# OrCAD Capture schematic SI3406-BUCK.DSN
size B; title: Si3404-Buck; rev: 2.2; note: SI3406-BUCK
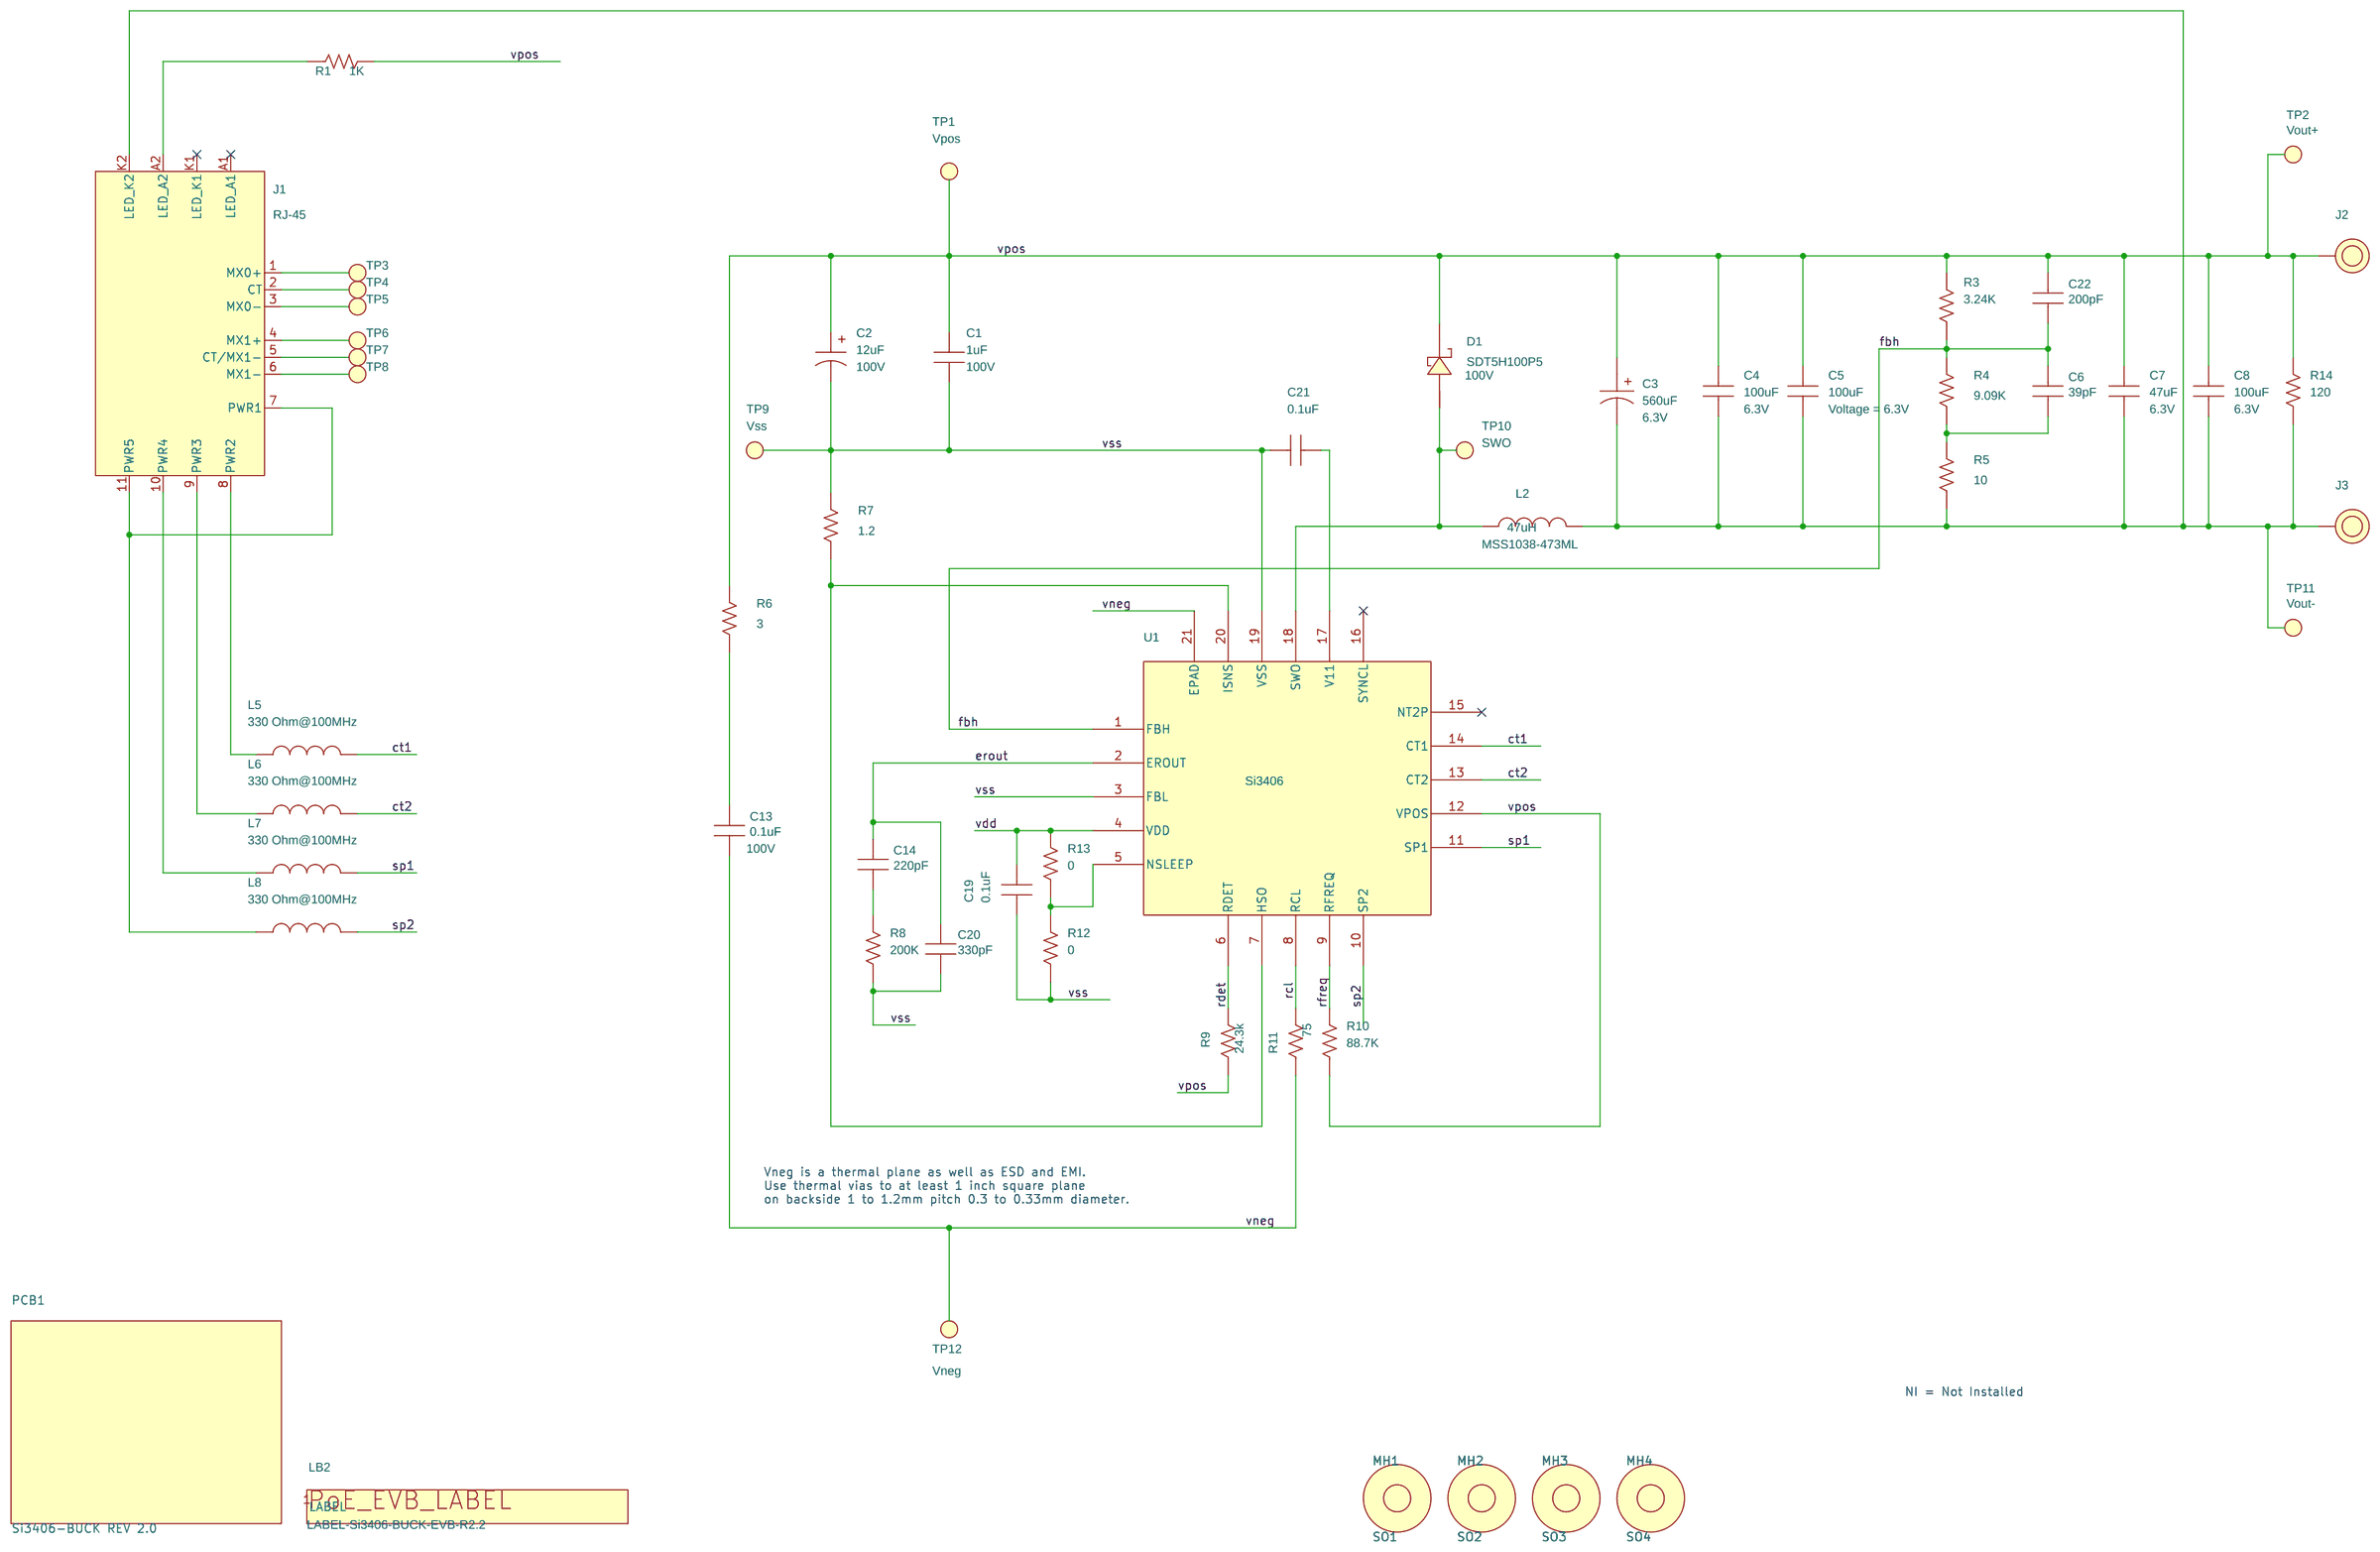
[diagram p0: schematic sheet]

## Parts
C1  1uF  [C1210]
C2  12uF  [C2.5X6.3MM-RAD]
C3  560uF  [C3.5X8MM-RAD]
C4  100uF  [C1210]
C5  100uF  [C1210]
C6  39pF  [C0805]
C7  47uF  [C0805]
C8  100uF  [C1210]
C13  0.1uF  [C0805]
C14  220pF  [C0805]
C19  0.1uF  [C0805]
C20  330pF  [C0805]
C21  0.1uF  [C0805]
C22  200pF  [C0805]
D1  SDT5H100P5  [POWERDI-5]
J1  RJ-45  [RJ45-SI-52004]
J2  BND_POST  [BANANA-JACK]
J3  BND_POST  [BANANA-JACK]
L2  47uH  [IND-MSS1038]
L5  330 Ohm@100MHz  [L0805]
L6  330 Ohm@100MHz  [L0805]
L7  330 Ohm@100MHz  [L0805]
L8  330 Ohm@100MHz  [L0805]
LB2  LABEL-Si3406-BUCK-EVB-R2.2  [PTL-14-717]
MH1  4-40  [MH-125NP]
MH2  4-40  [MH-125NP]
MH3  4-40  [MH-125NP]
MH4  4-40  [MH-125NP]
PCB1  Si3406-BUCK REV 2.0  [N/A]
R1  1K  [R0805]
R3  3.24K  [R0805]
R4  9.09K  [R0805]
R5  10  [R0805]
R6  3  [R0805]
R7  1.2  [R0805]
R8  200K  [R0805]
R9  24.3k  [R0805]
R10  88.7K  [R0805]
R11  75  [R0805]
R12  0  [R0805]
R13  0  [R0805]
R14  120  [R0805]
SO1  STANDOFF
SO2  STANDOFF
SO3  STANDOFF
SO4  STANDOFF
TP1  BLACK  [TESTPOINT]
TP2  BLACK  [TESTPOINT]
TP3  BLACK  [TESTPOINT]
TP4  BLACK  [TESTPOINT]
TP5  BLACK  [TESTPOINT]
TP6  BLACK  [TESTPOINT]
TP7  BLACK  [TESTPOINT]
TP8  BLACK  [TESTPOINT]
TP9  BLACK  [TESTPOINT]
TP10  BLACK  [TESTPOINT]
TP11  BLACK  [TESTPOINT]
TP12  BLACK  [TESTPOINT]
U1  Si3406  [QFN20N5X5P0.8]

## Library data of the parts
C1 = CAP_NP: CAP, 1uF, 100V, ±10%, X7R, 1210; Manufacturer: Venkel; ManufacturerPN: C1210X7R101-105K; SiLabsPN: C1210X7R101-105K; Tolerance: ±10%; Type: X7R; Voltage: 100V; Datasheet: PID_C.pdf
C2 = CAP_POL_ALT: CAP, 12uF, 100V, ±20%, AL, 6.3X11.2MM; Manufacturer: Panasonic; ManufacturerPN: EEUFC2A120; SiLabsPN: EEUFC2A120; Tolerance: ±20%; Type: Alum_Elec; Voltage: 100V; Datasheet: ABA0000CE22.pdf
C3 = CAP_POL: CAP, 560uF, 6.3V, ±20%, AL, 8.0X11.5MM; Manufacturer: Panasonic; ManufacturerPN: EEUFM0J561; Part_Type: CAP/POL; SiLabsPN: EEUFM0J561; Tolerance: ±20%; Type: Alum_Elec; Voltage: 6.3V; Datasheet: ABA0000CE108.pdf
C4 C5 C8 = CAP_NP: CAP, 100uF, 6.3V, ±10%, X5R, 1210; Manufacturer: Venkel; ManufacturerPN: C1210X5R6R3-107K; SiLabsPN: C1210X5R6R3-107K; Tolerance: ±10%; Type: X5R; Voltage: 6.3V; Datasheet: PID_C.pdf
C6 = CAP_NP: CAP, 39pF, 25V, ±1%, C0G, 0805; Manufacturer: Venkel; ManufacturerPN: C0805C0G250-390FNP; SiLabsPN: C0805C0G250-390F; Tolerance: ±1%; Type: C0G; Voltage: 25V; Datasheet: PID_C.pdf
C7 = CAP_NP: CAP, 47uF, 6.3V, ±20%, X5R, 0805; Manufacturer: Venkel; ManufacturerPN: C0805X5R6R3-476M; SiLabsPN: C0805X5R6R3-476M; Tolerance: ±20%; Type: X5R; Voltage: 6.3V; Datasheet: PID_C.pdf
C13 = CAP_NP: CAP, 0.1uF, 100V, ±10%, X7R, 0805; Manufacturer: Venkel; ManufacturerPN: C0805X7R101-104K; SiLabsPN: C0805X7R101-104K; Tolerance: ±10%; Type: X7R; Voltage: 100V; Datasheet: PID_C.pdf
C14 = CAP_NP: CAP, 220pF, 50V, ±1%, C0G, 0805; Manufacturer: Venkel; ManufacturerPN: C0805C0G500-221FNE; SiLabsPN: C0805C0G500-221F; Tolerance: ±1%; Type: C0G; Voltage: 50V; Datasheet: PID_C.pdf
C19 C21 = CAP_NP: CAP, 0.1uF, 16V, ±10%, X7R, 0805; Manufacturer: Venkel; ManufacturerPN: C0805X7R160-104K; SiLabsPN: C0805X7R160-104K; Tolerance: ±10%; Type: X7R; Voltage: 16V; Datasheet: PID_C.pdf
C20 = CAP_NP: CAP, 330pF, 50V, ±1%, C0G, 0805; Manufacturer: Venkel; ManufacturerPN: C0805C0G500-331F; SiLabsPN: C0805C0G500-331F; Tolerance: ±1%; Type: C0G; Voltage: 50V; Datasheet: PID_C.pdf
C22 = CAP_NP: CAP, 200pF, 50V, ±1%, C0G, 0805; Manufacturer: Venkel; ManufacturerPN: C0805C0G500-201FNE; SiLabsPN: C0805C0G500-201F; Tolerance: ±1%; Type: C0G; Voltage: 50V; Datasheet: PID_C.pdf
D1 = DIODE_SCHOTTKY_DUAL_ANODE_3PIN: DIO, SCHOTTKY, 100V, 5A, PowerDI-5; Manufacturer: Diodes Inc.; ManufacturerPN: SDT5H100P5-7; Rating: 5A; SiLabsPN: SDT5H100P5-7; Type: Schottky; Voltage: 100V; Datasheet: SDT5H100P5.pdf
J1 = MAGJACK_3: CONN, RJ-45, MAGJACK, 1 Port PoE; Manufacturer: Bel; ManufacturerPN: SI-52003-F; SiLabsPN: SI-52003-F; Type: Receptacle; Datasheet: SI-52003-F.pdf
J2 J3 = BINDING-POST: CONN, BANANA JACK, Threaded uninsulated; Manufacturer: ABBATRON HH SMITH; ManufacturerPN: 101; Part_Type: CON; Rating: 15A; SiLabsPN: 101; Type: BANANA; Datasheet: SD-101.pdf
L2 = INDUCTOR: INDUCTOR, POWER, Shielded, 47uH, ±20%, 1.6A, SMD; Manufacturer: Coilcraft; ManufacturerPN: MSS1038-473ML; Part_Type: IND/SMT; Rating: 1.6A; SiLabsPN: MSS1038-473ML; Tolerance: ±20%; Type: Shielded; Datasheet: mss1038.pdf
L5-L8 = Ferrite_Bead: FERRITE BEAD, 330 Ohm @100MHZ, 0805; Manufacturer: MuRata; ManufacturerPN: BLM21PG331SN1; Part_Type: IND/FB; Rating: 1500mA; SiLabsPN: BLM21PG331SN1; Type: SMT; Datasheet: Murata BLM Ferrites.pdf
LB2 = PoE_EVB_Label: LABEL, PDB, POLYIMIDE, WHITE, 1.00 in. X 0.187 in., FONT 2; Manufacturer: Skyworks; Type: POLYIMIDE, WHITE; Datasheet: Brady TLS2200 Label PTL-14-717.pdf
MH1-MH4 = SCREW-Small: HDW, SCREW, 4-40 x 1/4 in. Pan Head, Slotted, Nylon; Manufacturer: Richco Plastic Co; ManufacturerPN: NSS-4-4-01; SiLabsPN: NSS-4-4-01; Type: SCREW; Datasheet: RichcoPlasticCo_Screws.pdf
PCB1 = PCB: PCB, BARE BOARD, Si3406-BUCK REV 2.0; Manufacturer: Skyworks; Type: BARE PCB
R1 = RES_V: RES, 1K, 1/10W, ±1%, ThickFilm, 0805; Manufacturer: Venkel; ManufacturerPN: CR0805-10W-1001F; Part_Type: RES/SMT; Rating: 1/10W; SiLabsPN: CR0805-10W-1001F; Tolerance: ±1%; Type: ThickFilm; Datasheet: PID_CR.pdf
R3 = RES_V: RES, 3.24K, 1/8W, ±1%, ThickFilm, 0805; Manufacturer: Vishay; ManufacturerPN: CRCW08053K24FKEA; Part_Type: RES/SMT; Rating: 1/8W; SiLabsPN: CR0805-8W-3241F; Tolerance: ±1%; Type: ThickFilm; Datasheet: dcrcwe3-109170.pdf
R4 = RES: RES, 9.09K, 1/10W, ±25PPM, ±0.5%, ThinFilm, 0805; Manufacturer: Susumu; ManufacturerPN: RR1220P-9091-D-M; Rating: 1/10W; SiLabsPN: TFCR0805-10W-E-9091D; Tolerance: ±0.5%; Type: ±25PPM; Datasheet: n_catalog_partition05_en.pdf
R5 = RES: RES, 10 Ohm, 1/10W, ±1%, ThickFilm, 0805; Manufacturer: Venkel; ManufacturerPN: CR0805-10W-10R0F; Rating: 1/10W; SiLabsPN: CR0805-10W-10R0F; Tolerance: ±1%; Type: ThickFilm; Datasheet: PID_CR.pdf
R6 = RES: RES, 3 Ohm, 1/8W, ±1%, ThickFilm, 0805; Manufacturer: Venkel; ManufacturerPN: CR0805-8W-3R00FT; Rating: 1/8W; SiLabsPN: CR0805-8W-3R00F; Tolerance: ±1%; Type: ThickFilm; Datasheet: PID_CR.pdf
R7 = RES: RES, 1.2 Ohm, 1/10W, ±5%, ThickFilm, 0805; Manufacturer: Venkel; ManufacturerPN: CR0805-10W-1R2J; Rating: 1/10W; SiLabsPN: CR0805-10W-1R2J; Tolerance: ±5%; Type: ThickFilm; Datasheet: PID_CR.pdf
R8 = RES: RES, 200K, 1/10W, ±1%, ThickFilm, 0805; Manufacturer: Venkel; ManufacturerPN: CR0805-10W-2003F; Rating: 1/10W; SiLabsPN: CR0805-10W-2003F; Tolerance: ±1%; Type: ThickFilm; Datasheet: PID_CR.pdf
R9 = RES: RES, 24.3k, 1/8W, ±1%, ThickFilm, 0805; Manufacturer: vishay; ManufacturerPN: CRCW080524K3FKEA; Rating: 1/8W; SiLabsPN: CR0805-8W-2432F; Tolerance: ±1%; Type: ThickFilm; Datasheet: dcrcwe3-109170.pdf
R10 = RES: RES, 88.7K, 1/8W, ±1%, ThickFilm, 0805; Manufacturer: Vishay; ManufacturerPN: CRCW080588K7FKEA; Rating: 1/8W; SiLabsPN: CR0805-8W-8872F; Tolerance: ±1%; Type: ThickFilm; Datasheet: dcrcwe3-109170.pdf
R11 = RES: RES, 75 Ohm, 1/10W, ±1%, ThickFilm, 0805; Manufacturer: Venkel; ManufacturerPN: CR0805-10W-75R0F; Rating: 1/10W; SiLabsPN: CR0805-10W-75R0F; Tolerance: ±1%; Type: ThickFilm; Datasheet: PID_CR.pdf
R12 R13 = RES: RES, 0 Ohm, 2A, ThickFilm, 0805; Manufacturer: Venkel; ManufacturerPN: CR0805-10W-000; Rating: 2A; SiLabsPN: CR0805-10W-000; Type: ThickFilm; Datasheet: PID_CR.pdf
R14 = RES: RES, 120 Ohm, 1/10W, ±1%, ThickFilm, 0805; Manufacturer: Venkel; ManufacturerPN: CR0805-10W-1200F; Rating: 1/10W; SiLabsPN: CR0805-10W-1200F; Tolerance: ±1%; Type: ThickFilm; Datasheet: PID_CR.pdf
SO1-SO4 = STANDOFF: HDW, STANDOFF, 4-40 X 1/2" , Nylon; Manufacturer: SPC Technology; ManufacturerPN: 2397; SiLabsPN: 2397; Datasheet: SPC_Technology_spacers.pdf
TP1 = TEST_POINT: TESTPOINT, BLACK, 0.050" LOOP, PTH; Manufacturer: Keystone; ManufacturerPN: 5001; SiLabsPN: 5001; Silk: Vpos; Type: LOOP; Datasheet: Keystone_thm_datasheet.pdf
TP2 = TEST_POINT: TESTPOINT, BLACK, 0.050" LOOP, PTH; Manufacturer: Keystone; ManufacturerPN: 5001; SiLabsPN: 5001; Silk: Vout+; Type: LOOP; Datasheet: Keystone_thm_datasheet.pdf
TP3-TP8 = TEST_POINT: TESTPOINT, BLACK, 0.050" LOOP, PTH; Manufacturer: Keystone; ManufacturerPN: 5001; SiLabsPN: 5001; Silk: <Silk>; Type: LOOP; Datasheet: Keystone_thm_datasheet.pdf
TP9 = TEST_POINT: TESTPOINT, BLACK, 0.050" LOOP, PTH; Manufacturer: Keystone; ManufacturerPN: 5001; SiLabsPN: 5001; Silk: Vss; Type: LOOP; Datasheet: Keystone_thm_datasheet.pdf
TP10 = TEST_POINT: TESTPOINT, BLACK, 0.050" LOOP, PTH; Manufacturer: Keystone; ManufacturerPN: 5001; SiLabsPN: 5001; Silk: SWO; Type: LOOP; Datasheet: Keystone_thm_datasheet.pdf
TP11 = TEST_POINT: TESTPOINT, BLACK, 0.050" LOOP, PTH; Manufacturer: Keystone; ManufacturerPN: 5001; SiLabsPN: 5001; Silk: Vout-; Type: LOOP; Datasheet: Keystone_thm_datasheet.pdf
TP12 = TEST_POINT: TESTPOINT, BLACK, 0.050" LOOP, PTH; Manufacturer: Keystone; ManufacturerPN: 5001; SiLabsPN: 5001; Silk: Vneg; Type: LOOP; Datasheet: Keystone_thm_datasheet.pdf
U1 = Si3406: IC, FULLY-INTEGRATED 802.3-COMPLIANT PoE PD INTERFACE AND LOW-EMI SWITCHING REGULATOR, QFN20; Manufacturer: Skyworks; ManufacturerPN: Si3406-A-GM; SiLabsPN: Si3406-A-GM; Type: PD; Voltage: 120V; Datasheet: si3406x-datasheet.pdf

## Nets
vdd: C19.1 R13.2 U1.4(VDD)
vss: C1.1 C2.2 C19.2 C20.2 C21.1 R7.2 R8.1 R12.1 TP9.1(Point) U1.3(FBL) U1.19(VSS)
ct1: L5.2 U1.14(CT1)
ct2: L6.2 U1.13(CT2)
erout: C14.1 C20.1 U1.2(EROUT)
fbh: C6.1 C22.2 R3.2 R4.2 U1.1(FBH)
LABEL: LB2.1(LABEL)
rcl: R11.2 U1.8(RCL)
rdet: R9.2 U1.6(RDET)
rfreq: R10.2 U1.9(RFREQ)
sp1: L7.2 U1.11(SP1)
sp2: L8.2 U1.10(SP2)
vneg: C13.2 R11.1 TP12.1(Point) U1.21(EPAD)
vpos: C1.2 C2.1 C3.1 C4.1 C5.1 C7.2 C8.1 C22.1 D1.K(CATHODE) J2.1(BP) R1.1 R3.1 R6.2 R9.1 R10.1 R14.2 TP1.1(Point) TP2.1(Point) U1.12(VPOS)
N1344300: J1.A2(LED) R1.2
N1417589: J1.8(PWR2) L5.1
N1417594: J1.9(PWR3) L6.1
N1417609: J1.10(PWR4) L7.1
N1417624: J1.7(PWR1) J1.11(PWR5) L8.1
N1473877: C3.2 C4.2 C5.2 C7.1 C8.2 J1.K2(LED) J3.1(BP) L2.2 R5.1 R14.1 TP11.1(Point)
N1503918: D1.A1(ANODE) D1.A2(ANODE) L2.1 TP10.1(Point) U1.18(SWO)
N1514370: R7.1 U1.7(HSO) U1.20(ISNS)
N1518774: C14.2 R8.2
N1525569: J1.6(MX1-) TP8.1(Point)
N1525571: J1.4(MX1+) TP6.1(Point)
N1525573: J1.3(MX0-) TP5.1(Point)
N1525575: J1.2(CT) TP4.1(Point)
N1525577: J1.5(CT/MX1-) TP7.1(Point)
N1525579: J1.1(MX0+) TP3.1(Point)
N1548686: C6.2 R4.1 R5.2
N1584787: C21.2 U1.17(V11)
N1595132: C13.1 R6.1
N1596961: R12.2 R13.1 U1.5(NSLEEP)

Not connected (* = marked no-connect by the designer): J1 A1(LED)* K1(LED)*; U1 15(NT2P)* 16(SYNCL)*

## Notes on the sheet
- Vneg is a thermal plane as well as ESD and EMI.
  Use thermal vias to at least 1 inch square plane
  on backside 1 to 1.2mm pitch 0.3 to 0.33mm diameter.
- NI = Not Installed
